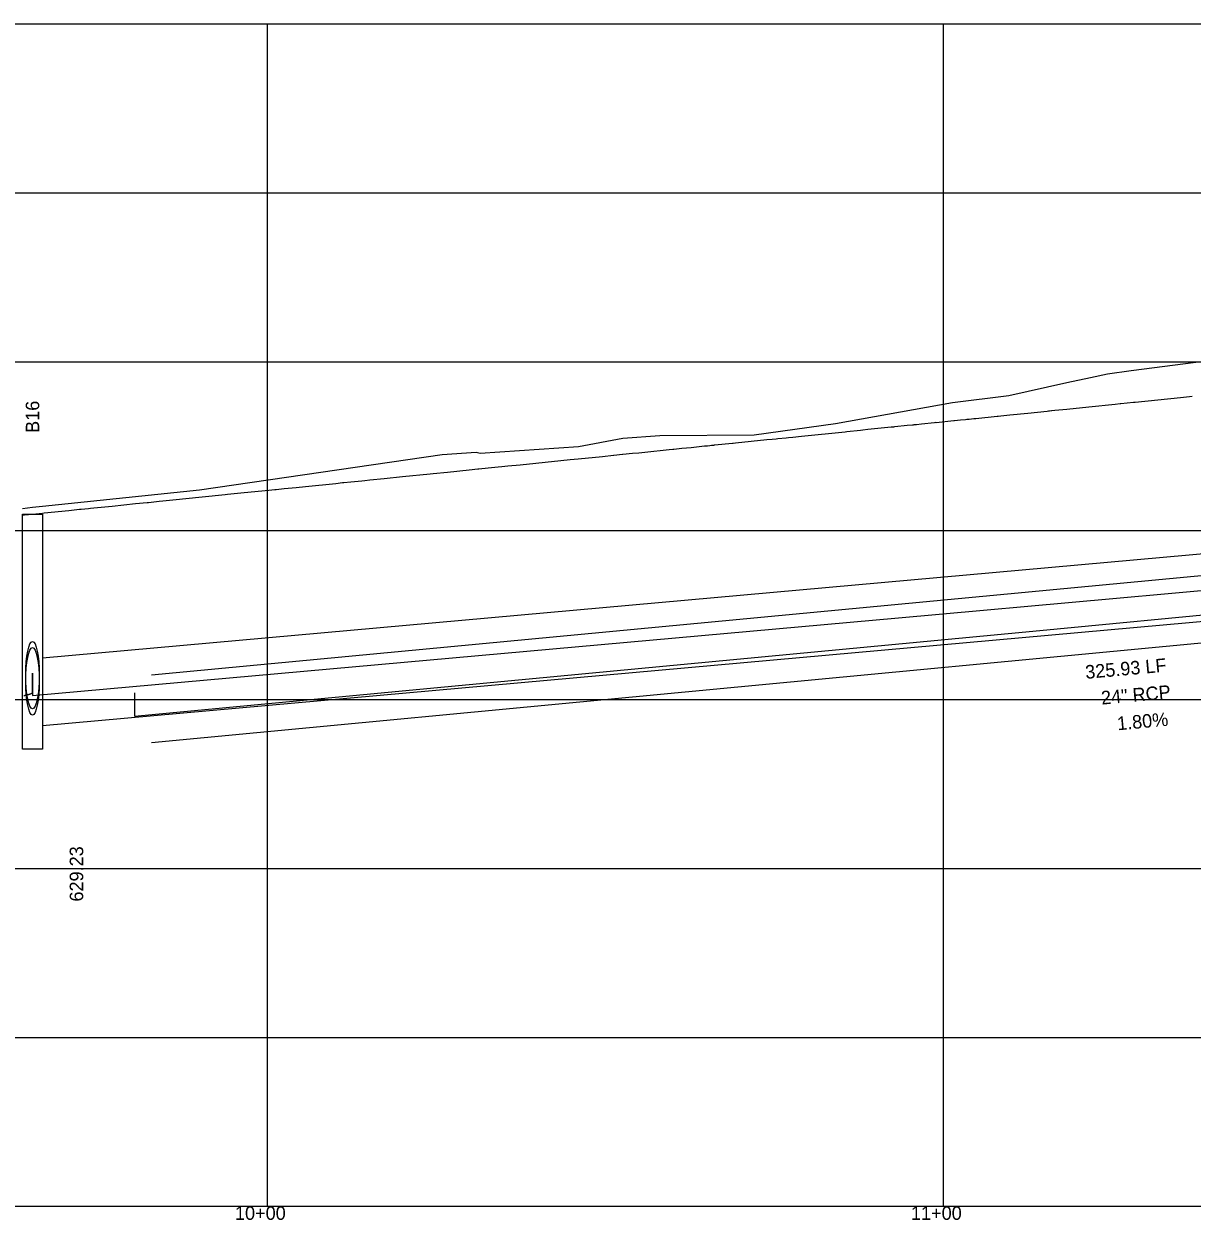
# Model space of a CAD drawing. Extents: x 2253035 to 2279930, y 13774972 to 13793443.
# Drawn here: x 2260990.4 to 2261163.2, y 13791296.5 to 13791473.6 of the extents above; entities that cross this region are included whole.
import ezdxf

# ---------------------------------------------------------------- set-up
doc = ezdxf.new("R2010")
doc.units = 0
for name, color, linetype in [('Default', 7, 'Continuous'), ('E_Utility_ATT_HH', 7, 'Continuous'), ('E_Utility_ATT_PR_PVC', 7, 'Continuous'), ('E_Utillity_Water_Water Line_12in', 7, 'Continuous'), ('E_Utillity_Water_Water Line_1in', 7, 'Continuous'), ('E_Utillity_Water_Water Line_4in', 7, 'Continuous'), ('E_Utillity_Water_Water Line_8in', 7, 'Continuous')]:
    doc.layers.add(name, color=color, linetype=linetype)

msp = doc.modelspace()

# ---------------------------------------------------------------- linework, layer by layer
at = {"layer": 'Default'}
for p, q in [((2261026.46, 13791298.56), (2261026.46, 13791473.56)), ((2261126.46, 13791298.56), (2261126.46, 13791473.56)), ((2260026.46, 13791448.56), (2261320.64, 13791448.56)), ((2260026.46, 13791423.56), (2261320.64, 13791423.56)), ((2260026.46, 13791398.56), (2261320.64, 13791398.56)), ((2260026.46, 13791373.56), (2261320.64, 13791373.56)), ((2260026.46, 13791348.56), (2261320.64, 13791348.56)), ((2260026.46, 13791323.56), (2261320.64, 13791323.56))]:
    msp.add_line(p, q, dxfattribs=at)
msp.add_lwpolyline([(2260026.46, 13791298.56), (2260026.46, 13791473.56), (2261320.64, 13791473.56), (2261320.64, 13791298.56)], close=True, dxfattribs=at)
at = {"layer": 'E_Utility_ATT_PR_PVC'}
for p, q in [((2260991.71, 13791377.47), (2260991.71, 13791374.14)), ((2261006.8, 13791374.55), (2261006.8, 13791371.1))]:
    msp.add_line(p, q, dxfattribs=at)
for points in [[(2260991.71, 13791374.14), (2261119.8, 13791385.67), (2261151.51, 13791388.53), (2261169, 13791390.11)], [(2261006.8, 13791371.1), (2261139.69, 13791383.71), (2261171.58, 13791386.75)], [(2260990.44, 13791374.15), (2260990.48, 13791374.16), (2260990.53, 13791374.17), (2260990.57, 13791374.18), (2260990.62, 13791374.19), (2260990.66, 13791374.2), (2260990.7, 13791374.21), (2260990.74, 13791374.22), (2260990.78, 13791374.23), (2260990.82, 13791374.24), (2260990.85, 13791374.25), (2260990.89, 13791374.26), (2260990.92, 13791374.27), (2260990.96, 13791374.28), (2260990.99, 13791374.29), (2260991.02, 13791374.3), (2260991.06, 13791374.3), (2260991.09, 13791374.31), (2260991.12, 13791374.32), (2260991.15, 13791374.33), (2260991.18, 13791374.34), (2260991.2, 13791374.35), (2260991.23, 13791374.36), (2260991.26, 13791374.36), (2260991.28, 13791374.37), (2260991.31, 13791374.38), (2260991.33, 13791374.39), (2260991.35, 13791374.39), (2260991.37, 13791374.4), (2260991.4, 13791374.41), (2260991.42, 13791374.42), (2260991.44, 13791374.42), (2260991.46, 13791374.43), (2260991.47, 13791374.44), (2260991.49, 13791374.45), (2260991.51, 13791374.45), (2260991.52, 13791374.46), (2260991.54, 13791374.47), (2260991.55, 13791374.47), (2260991.57, 13791374.48), (2260991.58, 13791374.49), (2260991.59, 13791374.49), (2260991.61, 13791374.5), (2260991.62, 13791374.51), (2260991.63, 13791374.51), (2260991.64, 13791374.52), (2260991.65, 13791374.52), (2260991.66, 13791374.53), (2260991.66, 13791374.54), (2260991.67, 13791374.54), (2260991.68, 13791374.55), (2260991.68, 13791374.55), (2260991.69, 13791374.56), (2260991.69, 13791374.57), (2260991.7, 13791374.57), (2260991.7, 13791374.58), (2260991.7, 13791374.58), (2260991.7, 13791374.59), (2260991.71, 13791374.59), (2260991.71, 13791374.6), (2260991.71, 13791374.6), (2260991.71, 13791377.47)]]:
    msp.add_lwpolyline(points, dxfattribs=at)
at = {"layer": 'E_Utillity_Water_Water Line_12in'}
msp.add_lwpolyline([(2260990.21, 13791401.01), (2260993.21, 13791401.01), (2260993.21, 13791366.21), (2260990.21, 13791366.21)], close=True, dxfattribs=at)
at = {"layer": 'E_Utillity_Water_Water Line_1in'}
msp.add_lwpolyline([(2260990.21, 13791401.86), (2260991.71, 13791402.03), (2260991.71, 13791402.03), (2260993.21, 13791402.2), (2260993.21, 13791402.2), (2261016.42, 13791404.61), (2261052.33, 13791409.81), (2261057.36, 13791410.2), (2261057.94, 13791410.05), (2261072.48, 13791411.04), (2261079.03, 13791412.27), (2261084.49, 13791412.64), (2261098.49, 13791412.72), (2261110.52, 13791414.44), (2261127.79, 13791417.55), (2261136.16, 13791418.54), (2261144.74, 13791420.49), (2261148.22, 13791421.23), (2261150.74, 13791421.75), (2261154.23, 13791422.28), (2261171.85, 13791424.51)], dxfattribs=at)
at = {"layer": 'E_Utillity_Water_Water Line_4in'}
for p, q in [((2260993.21, 13791379.72), (2261319.14, 13791409.06)), ((2261009.3, 13791377.21), (2261322.25, 13791406.91)), ((2260993.21, 13791369.72), (2261319.14, 13791399.06)), ((2261009.3, 13791367.21), (2261322.25, 13791396.91))]:
    msp.add_line(p, q, dxfattribs=at)
for centre in [(2260991.71, 13791377.18), (2260991.71, 13791376.27)]:
    msp.add_ellipse(centre, major_axis=(0, 5), ratio=0.2, dxfattribs=at)
at = {"layer": 'E_Utillity_Water_Water Line_8in'}
msp.add_lwpolyline([(2260990.21, 13791400.85), (2260990.54, 13791400.89), (2260991.71, 13791401.01), (2260991.71, 13791401.01), (2260993.21, 13791401.16), (2260993.21, 13791401.16), (2260993.44, 13791401.19), (2260997.1, 13791401.56), (2260998.68, 13791401.74), (2260998.89, 13791401.74), (2261000.01, 13791401.85), (2261000.3, 13791401.88), (2261000.77, 13791401.93), (2261003.49, 13791402.2), (2261006.96, 13791402.56), (2261008.68, 13791402.75), (2261008.87, 13791402.75), (2261010.44, 13791402.91), (2261010.98, 13791402.96), (2261012.47, 13791403.12), (2261016.83, 13791403.56), (2261020.22, 13791403.9), (2261020.58, 13791403.94), (2261023.04, 13791404.19), (2261026.69, 13791404.56), (2261027.57, 13791404.66), (2261027.67, 13791404.66), (2261027.75, 13791404.66), (2261028.96, 13791404.79), (2261030.72, 13791404.96), (2261032.09, 13791405.1), (2261036.56, 13791405.56), (2261037.58, 13791405.68), (2261037.67, 13791405.68), (2261037.75, 13791405.68), (2261038.82, 13791405.79), (2261040.42, 13791405.95), (2261040.86, 13791405.99), (2261041.6, 13791406.07), (2261043.72, 13791406.28), (2261046.42, 13791406.56), (2261050.52, 13791406.97), (2261050.99, 13791407.02), (2261053.1, 13791407.23), (2261056.29, 13791407.56), (2261057.61, 13791407.7), (2261057.67, 13791407.7), (2261057.72, 13791407.7), (2261059.1, 13791407.84), (2261060.62, 13791408), (2261061.13, 13791408.05), (2261062.04, 13791408.14), (2261063.84, 13791408.32), (2261066.15, 13791408.56), (2261071.27, 13791409.08), (2261072.44, 13791409.19), (2261076.02, 13791409.56), (2261077.66, 13791409.73), (2261077.67, 13791409.73), (2261077.69, 13791409.73), (2261078.97, 13791409.86), (2261079.06, 13791409.86), (2261080.45, 13791410.01), (2261081.41, 13791410.1), (2261082.28, 13791410.19), (2261085.88, 13791410.56), (2261086.41, 13791410.61), (2261086.41, 13791410.61), (2261086.53, 13791410.62), (2261086.54, 13791410.62), (2261086.57, 13791410.63), (2261086.57, 13791410.63), (2261086.6, 13791410.63), (2261087.76, 13791410.75), (2261089.14, 13791410.89), (2261091.1, 13791411.09), (2261091.55, 13791411.13), (2261091.9, 13791411.17), (2261092.15, 13791411.2), (2261092.53, 13791411.23), (2261092.56, 13791411.24), (2261092.58, 13791411.24), (2261092.58, 13791411.24), (2261095.25, 13791411.51), (2261095.32, 13791411.52), (2261095.36, 13791411.52), (2261095.37, 13791411.52), (2261095.37, 13791411.53), (2261095.68, 13791411.56), (2261100.34, 13791412.03), (2261101.13, 13791412.11), (2261101.72, 13791412.17), (2261101.95, 13791412.2), (2261103.2, 13791412.32), (2261103.54, 13791412.36), (2261104.18, 13791412.42), (2261105.49, 13791412.56), (2261111.91, 13791413.21), (2261112.18, 13791413.24), (2261114.19, 13791413.44), (2261114.54, 13791413.48), (2261115.3, 13791413.56), (2261118.73, 13791413.91), (2261119.11, 13791413.94), (2261119.25, 13791413.96), (2261121.09, 13791414.15), (2261121.87, 13791414.23), (2261122.04, 13791414.24), (2261122.11, 13791414.25), (2261122.5, 13791414.29), (2261123.2, 13791414.36), (2261125.12, 13791414.56), (2261125.34, 13791414.6), (2261125.34, 13791414.6), (2261125.35, 13791414.58), (2261125.37, 13791414.58), (2261125.37, 13791414.58), (2261125.37, 13791414.58), (2261125.37, 13791414.58), (2261125.38, 13791414.58), (2261128.01, 13791414.85), (2261128.11, 13791414.86), (2261129.01, 13791414.95), (2261129.73, 13791415.03), (2261129.91, 13791415.04), (2261130.09, 13791415.06), (2261130.19, 13791415.07), (2261130.22, 13791415.08), (2261130.26, 13791415.08), (2261130.28, 13791415.08), (2261130.95, 13791415.15), (2261131.25, 13791415.18), (2261134.39, 13791415.5), (2261134.56, 13791415.52), (2261134.93, 13791415.56), (2261136.31, 13791415.7), (2261138.96, 13791415.97), (2261141.79, 13791416.26), (2261142.02, 13791416.28), (2261142.16, 13791416.29), (2261142.45, 13791416.32), (2261142.49, 13791416.33), (2261142.96, 13791416.37), (2261144.74, 13791416.56), (2261147.99, 13791416.89), (2261151.85, 13791417.28), (2261152.59, 13791417.36), (2261152.69, 13791417.37), (2261154.56, 13791417.56), (2261154.63, 13791417.56), (2261154.81, 13791417.58), (2261161.55, 13791418.27), (2261162.88, 13791418.4), (2261163.28, 13791418.45)], dxfattribs=at)

# ---------------------------------------------------------------- texts
at = {"layer": 'Default'}
for s, p in [('10+00', (2261021.66, 13791296.56)), ('11+00', (2261121.66, 13791296.56))]:
    msp.add_text(s, height=2, dxfattribs=at).set_placement(p)
at = {"layer": 'E_Utility_ATT_HH'}
for s, rotation, p in [('B16', 90, (2260992.71, 13791413.03)), ('325.93 LF', 5.1428, (2261147.53, 13791376.62)), ('24" RCP', 5.1428, (2261149.88, 13791372.81)), ('1.80%', 5.1428, (2261152.24, 13791369.01)), ('629.23', 90, (2260999.21, 13791343.67))]:
    msp.add_text(s, height=2, rotation=rotation, dxfattribs=at).set_placement(p)

doc.saveas('drawing.dxf')
